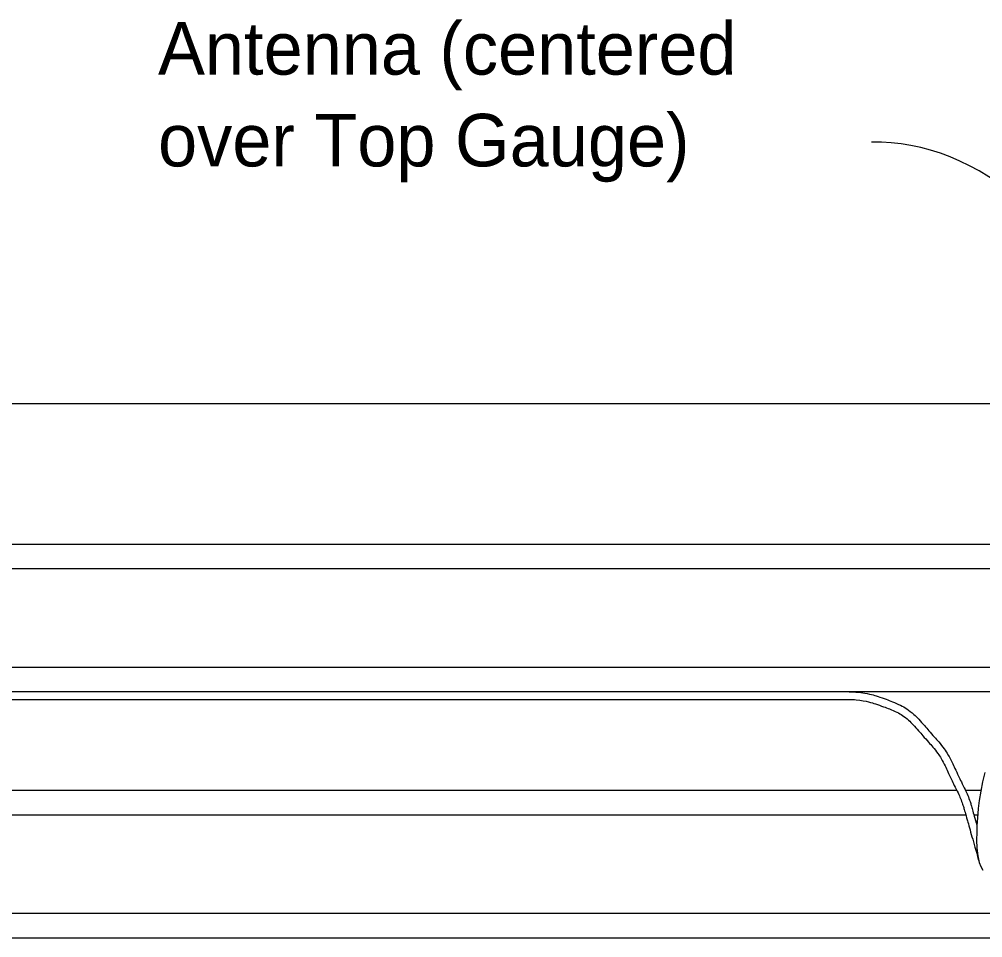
# Model space of a CAD drawing. Extents: x 0 to 36.1, y -3.7 to 15.
# Drawn here: x 13.382 to 15.23, y 11.346 to 13.107 of the extents above; entities that cross this region are included whole.
import ezdxf

# ---------------------------------------------------------------- set-up
doc = ezdxf.new("R2010")
doc.units = 0
for name, color, linetype in [('Leader', 7, 'Continuous'), ('Miscellaneous', 7, 'Continuous'), ('PileConc', 7, 'Continuous'), ('PlotBorder_dp', 7, 'Continuous'), ('PrestressSteel', 7, 'Continuous')]:
    doc.layers.add(name, color=color, linetype=linetype)

msp = doc.modelspace()

# ---------------------------------------------------------------- linework, layer by layer
at = {"layer": 'Leader'}
msp.add_ellipse((15.0739, 10.8491), major_axis=(0.0578, -2.0219), ratio=0.416452, start_param=2.427672, end_param=3.141387, dxfattribs=at)
at = {"layer": 'Miscellaneous'}
for p, q in [((10.9471, 11.8176), (14.9491, 11.8176)), ((10.9471, 11.8026), (14.9491, 11.8026))]:
    msp.add_line(p, q, dxfattribs=at)
msp.add_lwpolyline([(15.2337, 11.6623), (15.2294, 11.6445), (15.2259, 11.6266), (15.2231, 11.609), (15.2212, 11.5936), (15.2202, 11.5838), (15.2195, 11.5755), (15.219, 11.5686), (15.2185, 11.5597), (15.2181, 11.5478), (15.218, 11.5335), (15.2186, 11.5176), (15.2201, 11.5028), (15.2228, 11.4902), (15.2257, 11.4821), (15.2297, 11.4754)], dxfattribs=at)
for points in [[(14.9491, 11.8176), (14.9586, 11.8176), (14.9684, 11.8178), (14.988, 11.8169), (14.9981, 11.8162), (15.0179, 11.812), (15.0274, 11.8088), (15.0459, 11.8024), (15.0552, 11.7991), (15.0736, 11.791), (15.0826, 11.7861), (15.0991, 11.7732), (15.106, 11.7658), (15.1191, 11.7513), (15.1253, 11.7439), (15.1378, 11.7296), (15.1444, 11.7225), (15.1568, 11.7069), (15.1624, 11.6982), (15.1717, 11.6806), (15.1757, 11.6717), (15.1837, 11.6544), (15.1879, 11.6459), (15.1965, 11.6285), (15.2007, 11.6196), (15.2059, 11.6054), (15.2073, 11.6005), (15.2099, 11.5913), (15.2132, 11.5796), (15.2166, 11.5679), (15.2186, 11.5608)], [(14.9491, 11.8026), (14.9685, 11.8026), (14.9873, 11.8032), (15.0137, 11.7975), (15.0226, 11.7946), (15.0407, 11.7883), (15.0498, 11.7851), (15.0667, 11.7776), (15.0746, 11.7733), (15.0886, 11.7623), (15.0952, 11.7554), (15.1077, 11.7415), (15.1138, 11.7342), (15.1267, 11.7195), (15.1331, 11.7126), (15.1446, 11.6982), (15.1495, 11.6906), (15.1582, 11.6742), (15.162, 11.6656), (15.1701, 11.648), (15.1745, 11.6392), (15.183, 11.622), (15.1869, 11.6136), (15.1916, 11.6007), (15.1929, 11.5964), (15.1955, 11.5872), (15.1994, 11.5733), (15.2086, 11.541), (15.2165, 11.5133), (15.2218, 11.4948)]]:
    msp.add_open_spline(points, degree=3, dxfattribs=at)
at = {"layer": 'PileConc'}
msp.add_line((19.6923, 12.3693), (10.9471, 12.3693), dxfattribs=at)
at = {"layer": 'PrestressSteel'}
for p, q in [((10.9471, 12.1005), (19.7548, 12.1005)), ((10.9471, 12.0536), (15.3647, 12.0536)), ((10.9471, 11.8645), (15.4196, 11.8645)), ((10.9471, 11.8176), (15.4146, 11.8176)), ((10.9471, 11.6286), (15.1797, 11.6286)), ((15.1963, 11.6286), (15.2262, 11.6286)), ((10.9471, 11.5817), (15.197, 11.5817)), ((15.2126, 11.5817), (15.22, 11.5817)), ((10.9471, 11.3927), (15.3173, 11.3927)), ((10.9471, 11.3458), (15.3065, 11.3458))]:
    msp.add_line(p, q, dxfattribs=at)

# ---------------------------------------------------------------- texts
at = {"layer": 'PlotBorder_dp'}
for s, p in [('Antenna (centered', (13.6485, 13.0007)), ('over Top Gauge)', (13.6485, 12.8247))]:
    msp.add_text(s, height=0.1008, dxfattribs=at).set_placement(p)

doc.saveas('drawing.dxf')
